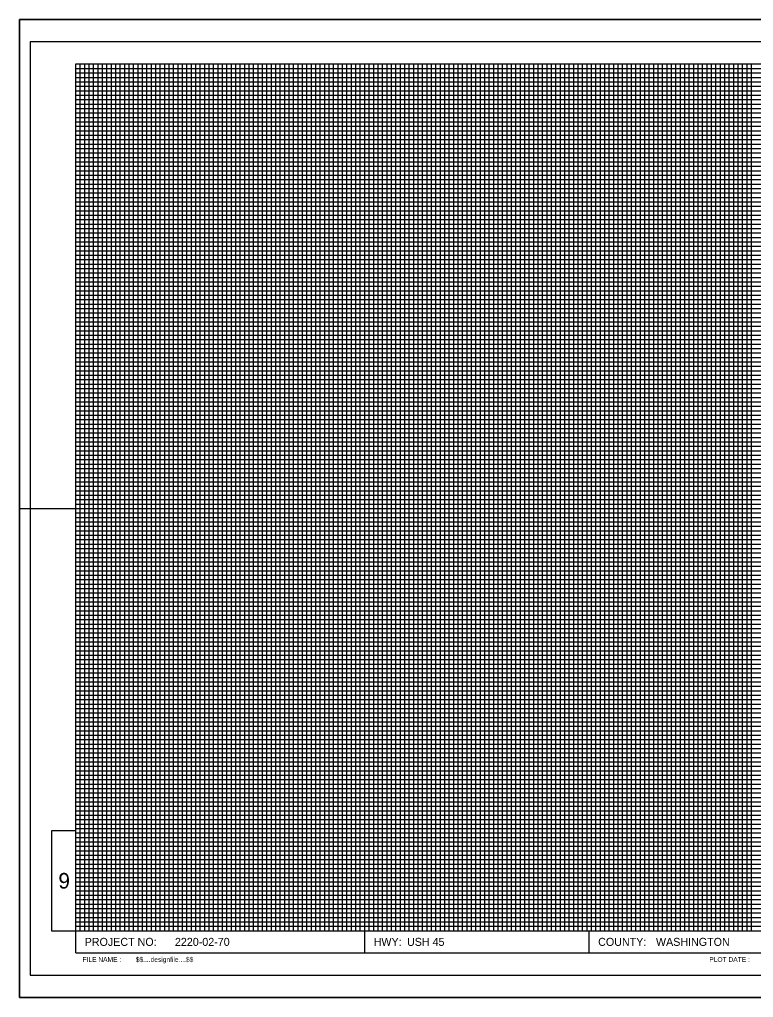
# Model space of a CAD drawing. Extents: x -1703 to 1697, y -1124 to 1076.
# Drawn here: x -1703 to -52, y -1124 to 1076 of the extents above; entities that cross this region are included whole.
import ezdxf

# ---------------------------------------------------------------- set-up
doc = ezdxf.new("R2010")
doc.units = 0
for name, color, linetype in [('E_PROF_Grid', 7, 'Continuous'), ('E_PROF_GridMin', 7, 'Continuous'), ('PLT_Sheet_Border', 7, 'Continuous'), ('PLT_Sheet_Info', 7, 'Continuous')]:
    doc.layers.add(name, color=color, linetype=linetype)

msp = doc.modelspace()

# ---------------------------------------------------------------- linework, layer by layer
at = {"layer": 'E_PROF_Grid'}
for p, q in [((-1526.4, -973.7), (-1526.4, 976.3)), ((-1476.4, -973.7), (-1476.4, 976.3)), ((-1426.4, -973.7), (-1426.4, 976.3)), ((-1376.4, -973.7), (-1376.4, 976.3)), ((-1326.4, -973.7), (-1326.4, 976.3)), ((-1276.4, -973.7), (-1276.4, 976.3)), ((-1226.4, -973.7), (-1226.4, 976.3)), ((-1176.4, -973.7), (-1176.4, 976.3)), ((-1126.4, -973.7), (-1126.4, 976.3)), ((-1076.4, -973.7), (-1076.4, 976.3)), ((-1026.4, -973.7), (-1026.4, 976.3)), ((-976.4, -973.7), (-976.4, 976.3)), ((-926.4, -973.7), (-926.4, 976.3)), ((-876.4, -973.7), (-876.4, 976.3)), ((-826.4, -973.7), (-826.4, 976.3)), ((-776.4, -973.7), (-776.4, 976.3)), ((-726.4, -973.7), (-726.4, 976.3)), ((-676.4, -973.7), (-676.4, 976.3)), ((-626.4, -973.7), (-626.4, 976.3)), ((-576.4, -973.7), (-576.4, 976.3)), ((-526.4, -973.7), (-526.4, 976.3)), ((-476.4, -973.7), (-476.4, 976.3)), ((-426.4, -973.7), (-426.4, 976.3)), ((-376.4, -973.7), (-376.4, 976.3)), ((-326.4, -973.7), (-326.4, 976.3)), ((-276.4, -973.7), (-276.4, 976.3)), ((-226.4, -973.7), (-226.4, 976.3)), ((-176.4, -973.7), (-176.4, 976.3)), ((-126.4, -973.7), (-126.4, 976.3)), ((-76.4, -973.7), (-76.4, 976.3)), ((-1576.4, 926.3), (1573.6, 926.3)), ((-1576.4, 876.3), (1573.6, 876.3)), ((-1576.4, 826.3), (1573.6, 826.3)), ((-1576.4, 776.3), (1573.6, 776.3)), ((-1576.4, 726.3), (1573.6, 726.3)), ((-1576.4, 676.3), (1573.6, 676.3)), ((-1576.4, 626.3), (1573.6, 626.3)), ((-1576.4, 576.3), (1573.6, 576.3)), ((-1576.4, 526.3), (1573.6, 526.3)), ((-1576.4, 476.3), (1573.6, 476.3)), ((-1576.4, 426.3), (1573.6, 426.3)), ((-1576.4, 376.3), (1573.6, 376.3)), ((-1576.4, 326.3), (1573.6, 326.3)), ((-1576.4, 276.3), (1573.6, 276.3)), ((-1576.4, 226.3), (1573.6, 226.3)), ((-1576.4, 176.3), (1573.6, 176.3)), ((-1576.4, 126.3), (1573.6, 126.3)), ((-1576.4, 76.3), (1573.6, 76.3)), ((-1576.4, 26.3), (1573.6, 26.3)), ((-1576.4, -23.7), (1573.6, -23.7)), ((-1576.4, -73.7), (1573.6, -73.7)), ((-1576.4, -123.7), (1573.6, -123.7)), ((-1576.4, -173.7), (1573.6, -173.7)), ((-1576.4, -223.7), (1573.6, -223.7)), ((-1576.4, -273.7), (1573.6, -273.7)), ((-1576.4, -323.7), (1573.6, -323.7)), ((-1576.4, -373.7), (1573.6, -373.7)), ((-1576.4, -423.7), (1573.6, -423.7)), ((-1576.4, -473.7), (1573.6, -473.7)), ((-1576.4, -523.7), (1573.6, -523.7)), ((-1576.4, -573.7), (1573.6, -573.7)), ((-1576.4, -623.7), (1573.6, -623.7)), ((-1576.4, -673.7), (1573.6, -673.7)), ((-1576.4, -723.7), (1573.6, -723.7)), ((-1576.4, -773.7), (1573.6, -773.7)), ((-1576.4, -823.7), (1573.6, -823.7)), ((-1576.4, -873.7), (1573.6, -873.7)), ((-1576.4, -923.7), (1573.6, -923.7))]:
    msp.add_line(p, q, dxfattribs=at)
at = {"layer": 'E_PROF_GridMin'}
for p, q in [((-1566.4, -973.7), (-1566.4, 976.3)), ((-1556.4, -973.7), (-1556.4, 976.3)), ((-1546.4, -973.7), (-1546.4, 976.3)), ((-1536.4, -973.7), (-1536.4, 976.3)), ((-1516.4, -973.7), (-1516.4, 976.3)), ((-1506.4, -973.7), (-1506.4, 976.3)), ((-1496.4, -973.7), (-1496.4, 976.3)), ((-1486.4, -973.7), (-1486.4, 976.3)), ((-1466.4, -973.7), (-1466.4, 976.3)), ((-1456.4, -973.7), (-1456.4, 976.3)), ((-1446.4, -973.7), (-1446.4, 976.3)), ((-1436.4, -973.7), (-1436.4, 976.3)), ((-1416.4, -973.7), (-1416.4, 976.3)), ((-1406.4, -973.7), (-1406.4, 976.3)), ((-1396.4, -973.7), (-1396.4, 976.3)), ((-1386.4, -973.7), (-1386.4, 976.3)), ((-1366.4, -973.7), (-1366.4, 976.3)), ((-1356.4, -973.7), (-1356.4, 976.3)), ((-1346.4, -973.7), (-1346.4, 976.3)), ((-1336.4, -973.7), (-1336.4, 976.3)), ((-1316.4, -973.7), (-1316.4, 976.3)), ((-1306.4, -973.7), (-1306.4, 976.3)), ((-1296.4, -973.7), (-1296.4, 976.3)), ((-1286.4, -973.7), (-1286.4, 976.3)), ((-1266.4, -973.7), (-1266.4, 976.3)), ((-1256.4, -973.7), (-1256.4, 976.3)), ((-1246.4, -973.7), (-1246.4, 976.3)), ((-1236.4, -973.7), (-1236.4, 976.3)), ((-1216.4, -973.7), (-1216.4, 976.3)), ((-1206.4, -973.7), (-1206.4, 976.3)), ((-1196.4, -973.7), (-1196.4, 976.3)), ((-1186.4, -973.7), (-1186.4, 976.3)), ((-1166.4, -973.7), (-1166.4, 976.3)), ((-1156.4, -973.7), (-1156.4, 976.3)), ((-1146.4, -973.7), (-1146.4, 976.3)), ((-1136.4, -973.7), (-1136.4, 976.3)), ((-1116.4, -973.7), (-1116.4, 976.3)), ((-1106.4, -973.7), (-1106.4, 976.3)), ((-1096.4, -973.7), (-1096.4, 976.3)), ((-1086.4, -973.7), (-1086.4, 976.3)), ((-1066.4, -973.7), (-1066.4, 976.3)), ((-1056.4, -973.7), (-1056.4, 976.3)), ((-1046.4, -973.7), (-1046.4, 976.3)), ((-1036.4, -973.7), (-1036.4, 976.3)), ((-1016.4, -973.7), (-1016.4, 976.3)), ((-1006.4, -973.7), (-1006.4, 976.3)), ((-996.4, -973.7), (-996.4, 976.3)), ((-986.4, -973.7), (-986.4, 976.3)), ((-966.4, -973.7), (-966.4, 976.3)), ((-956.4, -973.7), (-956.4, 976.3)), ((-946.4, -973.7), (-946.4, 976.3)), ((-936.4, -973.7), (-936.4, 976.3)), ((-916.4, -973.7), (-916.4, 976.3)), ((-906.4, -973.7), (-906.4, 976.3)), ((-896.4, -973.7), (-896.4, 976.3)), ((-886.4, -973.7), (-886.4, 976.3)), ((-866.4, -973.7), (-866.4, 976.3)), ((-856.4, -973.7), (-856.4, 976.3)), ((-846.4, -973.7), (-846.4, 976.3)), ((-836.4, -973.7), (-836.4, 976.3)), ((-816.4, -973.7), (-816.4, 976.3)), ((-806.4, -973.7), (-806.4, 976.3)), ((-796.4, -973.7), (-796.4, 976.3)), ((-786.4, -973.7), (-786.4, 976.3)), ((-766.4, -973.7), (-766.4, 976.3)), ((-756.4, -973.7), (-756.4, 976.3)), ((-746.4, -973.7), (-746.4, 976.3)), ((-736.4, -973.7), (-736.4, 976.3)), ((-716.4, -973.7), (-716.4, 976.3)), ((-706.4, -973.7), (-706.4, 976.3)), ((-696.4, -973.7), (-696.4, 976.3)), ((-686.4, -973.7), (-686.4, 976.3)), ((-666.4, -973.7), (-666.4, 976.3)), ((-656.4, -973.7), (-656.4, 976.3)), ((-646.4, -973.7), (-646.4, 976.3)), ((-636.4, -973.7), (-636.4, 976.3)), ((-616.4, -973.7), (-616.4, 976.3)), ((-606.4, -973.7), (-606.4, 976.3)), ((-596.4, -973.7), (-596.4, 976.3)), ((-586.4, -973.7), (-586.4, 976.3)), ((-566.4, -973.7), (-566.4, 976.3)), ((-556.4, -973.7), (-556.4, 976.3)), ((-546.4, -973.7), (-546.4, 976.3)), ((-536.4, -973.7), (-536.4, 976.3)), ((-516.4, -973.7), (-516.4, 976.3)), ((-506.4, -973.7), (-506.4, 976.3)), ((-496.4, -973.7), (-496.4, 976.3)), ((-486.4, -973.7), (-486.4, 976.3)), ((-466.4, -973.7), (-466.4, 976.3)), ((-456.4, -973.7), (-456.4, 976.3)), ((-446.4, -973.7), (-446.4, 976.3)), ((-436.4, -973.7), (-436.4, 976.3)), ((-416.4, -973.7), (-416.4, 976.3)), ((-406.4, -973.7), (-406.4, 976.3)), ((-396.4, -973.7), (-396.4, 976.3)), ((-386.4, -973.7), (-386.4, 976.3)), ((-366.4, -973.7), (-366.4, 976.3)), ((-356.4, -973.7), (-356.4, 976.3)), ((-346.4, -973.7), (-346.4, 976.3)), ((-336.4, -973.7), (-336.4, 976.3)), ((-316.4, -973.7), (-316.4, 976.3)), ((-306.4, -973.7), (-306.4, 976.3)), ((-296.4, -973.7), (-296.4, 976.3)), ((-286.4, -973.7), (-286.4, 976.3)), ((-266.4, -973.7), (-266.4, 976.3)), ((-256.4, -973.7), (-256.4, 976.3)), ((-246.4, -973.7), (-246.4, 976.3)), ((-236.4, -973.7), (-236.4, 976.3)), ((-216.4, -973.7), (-216.4, 976.3)), ((-206.4, -973.7), (-206.4, 976.3)), ((-196.4, -973.7), (-196.4, 976.3)), ((-186.4, -973.7), (-186.4, 976.3)), ((-166.4, -973.7), (-166.4, 976.3)), ((-156.4, -973.7), (-156.4, 976.3)), ((-146.4, -973.7), (-146.4, 976.3)), ((-136.4, -973.7), (-136.4, 976.3)), ((-116.4, -973.7), (-116.4, 976.3)), ((-106.4, -973.7), (-106.4, 976.3)), ((-96.4, -973.7), (-96.4, 976.3)), ((-86.4, -973.7), (-86.4, 976.3)), ((-66.4, -973.7), (-66.4, 976.3)), ((-56.4, -973.7), (-56.4, 976.3)), ((-1576.4, 966.3), (1573.6, 966.3)), ((-1576.4, 956.3), (1573.6, 956.3)), ((-1576.4, 946.3), (1573.6, 946.3)), ((-1576.4, 936.3), (1573.6, 936.3)), ((-1576.4, 916.3), (1573.6, 916.3)), ((-1576.4, 906.3), (1573.6, 906.3)), ((-1576.4, 896.3), (1573.6, 896.3)), ((-1576.4, 886.3), (1573.6, 886.3)), ((-1576.4, 866.3), (1573.6, 866.3)), ((-1576.4, 856.3), (1573.6, 856.3)), ((-1576.4, 846.3), (1573.6, 846.3)), ((-1576.4, 836.3), (1573.6, 836.3)), ((-1576.4, 816.3), (1573.6, 816.3)), ((-1576.4, 806.3), (1573.6, 806.3)), ((-1576.4, 796.3), (1573.6, 796.3)), ((-1576.4, 786.3), (1573.6, 786.3)), ((-1576.4, 766.3), (1573.6, 766.3)), ((-1576.4, 756.3), (1573.6, 756.3)), ((-1576.4, 746.3), (1573.6, 746.3)), ((-1576.4, 736.3), (1573.6, 736.3)), ((-1576.4, 716.3), (1573.6, 716.3)), ((-1576.4, 706.3), (1573.6, 706.3)), ((-1576.4, 696.3), (1573.6, 696.3)), ((-1576.4, 686.3), (1573.6, 686.3)), ((-1576.4, 666.3), (1573.6, 666.3)), ((-1576.4, 656.3), (1573.6, 656.3)), ((-1576.4, 646.3), (1573.6, 646.3)), ((-1576.4, 636.3), (1573.6, 636.3)), ((-1576.4, 616.3), (1573.6, 616.3)), ((-1576.4, 606.3), (1573.6, 606.3)), ((-1576.4, 596.3), (1573.6, 596.3)), ((-1576.4, 586.3), (1573.6, 586.3)), ((-1576.4, 566.3), (1573.6, 566.3)), ((-1576.4, 556.3), (1573.6, 556.3)), ((-1576.4, 546.3), (1573.6, 546.3)), ((-1576.4, 536.3), (1573.6, 536.3)), ((-1576.4, 516.3), (1573.6, 516.3)), ((-1576.4, 506.3), (1573.6, 506.3)), ((-1576.4, 496.3), (1573.6, 496.3)), ((-1576.4, 486.3), (1573.6, 486.3)), ((-1576.4, 466.3), (1573.6, 466.3)), ((-1576.4, 456.3), (1573.6, 456.3)), ((-1576.4, 446.3), (1573.6, 446.3)), ((-1576.4, 436.3), (1573.6, 436.3)), ((-1576.4, 416.3), (1573.6, 416.3)), ((-1576.4, 406.3), (1573.6, 406.3)), ((-1576.4, 396.3), (1573.6, 396.3)), ((-1576.4, 386.3), (1573.6, 386.3)), ((-1576.4, 366.3), (1573.6, 366.3)), ((-1576.4, 356.3), (1573.6, 356.3)), ((-1576.4, 346.3), (1573.6, 346.3)), ((-1576.4, 336.3), (1573.6, 336.3)), ((-1576.4, 316.3), (1573.6, 316.3)), ((-1576.4, 306.3), (1573.6, 306.3)), ((-1576.4, 296.3), (1573.6, 296.3)), ((-1576.4, 286.3), (1573.6, 286.3)), ((-1576.4, 266.3), (1573.6, 266.3)), ((-1576.4, 256.3), (1573.6, 256.3)), ((-1576.4, 246.3), (1573.6, 246.3)), ((-1576.4, 236.3), (1573.6, 236.3)), ((-1576.4, 216.3), (1573.6, 216.3)), ((-1576.4, 206.3), (1573.6, 206.3)), ((-1576.4, 196.3), (1573.6, 196.3)), ((-1576.4, 186.3), (1573.6, 186.3)), ((-1576.4, 166.3), (1573.6, 166.3)), ((-1576.4, 156.3), (1573.6, 156.3)), ((-1576.4, 146.3), (1573.6, 146.3)), ((-1576.4, 136.3), (1573.6, 136.3)), ((-1576.4, 116.3), (1573.6, 116.3)), ((-1576.4, 106.3), (1573.6, 106.3)), ((-1576.4, 96.3), (1573.6, 96.3)), ((-1576.4, 86.3), (1573.6, 86.3)), ((-1576.4, 66.3), (1573.6, 66.3)), ((-1576.4, 56.3), (1573.6, 56.3)), ((-1576.4, 46.3), (1573.6, 46.3)), ((-1576.4, 36.3), (1573.6, 36.3)), ((-1576.4, 16.3), (1573.6, 16.3)), ((-1576.4, 6.3), (1573.6, 6.3)), ((-1576.4, -3.7), (1573.6, -3.7)), ((-1576.4, -13.7), (1573.6, -13.7)), ((-1576.4, -33.7), (1573.6, -33.7)), ((-1576.4, -43.7), (1573.6, -43.7)), ((-1576.4, -53.7), (1573.6, -53.7)), ((-1576.4, -63.7), (1573.6, -63.7)), ((-1576.4, -83.7), (1573.6, -83.7)), ((-1576.4, -93.7), (1573.6, -93.7)), ((-1576.4, -103.7), (1573.6, -103.7)), ((-1576.4, -113.7), (1573.6, -113.7)), ((-1576.4, -133.7), (1573.6, -133.7)), ((-1576.4, -143.7), (1573.6, -143.7)), ((-1576.4, -153.7), (1573.6, -153.7)), ((-1576.4, -163.7), (1573.6, -163.7)), ((-1576.4, -183.7), (1573.6, -183.7)), ((-1576.4, -193.7), (1573.6, -193.7)), ((-1576.4, -203.7), (1573.6, -203.7)), ((-1576.4, -213.7), (1573.6, -213.7)), ((-1576.4, -233.7), (1573.6, -233.7)), ((-1576.4, -243.7), (1573.6, -243.7)), ((-1576.4, -253.7), (1573.6, -253.7)), ((-1576.4, -263.7), (1573.6, -263.7)), ((-1576.4, -283.7), (1573.6, -283.7)), ((-1576.4, -293.7), (1573.6, -293.7)), ((-1576.4, -303.7), (1573.6, -303.7)), ((-1576.4, -313.7), (1573.6, -313.7)), ((-1576.4, -333.7), (1573.6, -333.7)), ((-1576.4, -343.7), (1573.6, -343.7)), ((-1576.4, -353.7), (1573.6, -353.7)), ((-1576.4, -363.7), (1573.6, -363.7)), ((-1576.4, -383.7), (1573.6, -383.7)), ((-1576.4, -393.7), (1573.6, -393.7)), ((-1576.4, -403.7), (1573.6, -403.7)), ((-1576.4, -413.7), (1573.6, -413.7)), ((-1576.4, -433.7), (1573.6, -433.7)), ((-1576.4, -443.7), (1573.6, -443.7)), ((-1576.4, -453.7), (1573.6, -453.7)), ((-1576.4, -463.7), (1573.6, -463.7)), ((-1576.4, -483.7), (1573.6, -483.7)), ((-1576.4, -493.7), (1573.6, -493.7)), ((-1576.4, -503.7), (1573.6, -503.7)), ((-1576.4, -513.7), (1573.6, -513.7)), ((-1576.4, -533.7), (1573.6, -533.7)), ((-1576.4, -543.7), (1573.6, -543.7)), ((-1576.4, -553.7), (1573.6, -553.7)), ((-1576.4, -563.7), (1573.6, -563.7)), ((-1576.4, -583.7), (1573.6, -583.7)), ((-1576.4, -593.7), (1573.6, -593.7)), ((-1576.4, -603.7), (1573.6, -603.7)), ((-1576.4, -613.7), (1573.6, -613.7)), ((-1576.4, -633.7), (1573.6, -633.7)), ((-1576.4, -643.7), (1573.6, -643.7)), ((-1576.4, -653.7), (1573.6, -653.7)), ((-1576.4, -663.7), (1573.6, -663.7)), ((-1576.4, -683.7), (1573.6, -683.7)), ((-1576.4, -693.7), (1573.6, -693.7)), ((-1576.4, -703.7), (1573.6, -703.7)), ((-1576.4, -713.7), (1573.6, -713.7)), ((-1576.4, -733.7), (1573.6, -733.7)), ((-1576.4, -743.7), (1573.6, -743.7)), ((-1576.4, -753.7), (1573.6, -753.7)), ((-1576.4, -763.7), (1573.6, -763.7)), ((-1576.4, -783.7), (1573.6, -783.7)), ((-1576.4, -793.7), (1573.6, -793.7)), ((-1576.4, -803.7), (1573.6, -803.7)), ((-1576.4, -813.7), (1573.6, -813.7)), ((-1576.4, -833.7), (1573.6, -833.7)), ((-1576.4, -843.7), (1573.6, -843.7)), ((-1576.4, -853.7), (1573.6, -853.7)), ((-1576.4, -863.7), (1573.6, -863.7)), ((-1576.4, -883.7), (1573.6, -883.7)), ((-1576.4, -893.7), (1573.6, -893.7)), ((-1576.4, -903.7), (1573.6, -903.7)), ((-1576.4, -913.7), (1573.6, -913.7)), ((-1576.4, -933.7), (1573.6, -933.7)), ((-1576.4, -943.7), (1573.6, -943.7)), ((-1576.4, -953.7), (1573.6, -953.7)), ((-1576.4, -963.7), (1573.6, -963.7))]:
    msp.add_line(p, q, dxfattribs=at)
at = {"layer": 'PLT_Sheet_Border'}
for points in [[(-1702.9, 1076.3), (1697.1, 1076.3), (1697.1, -1123.7), (-1702.9, -1123.7)], [(-1702.9, -1123.7), (1697.1, -1123.7), (1697.1, 1076.3), (-1702.9, 1076.3)], [(-1678.9, -1073.7), (1631.1, -1073.7), (1631.1, 1026.3), (-1678.9, 1026.3)]]:
    msp.add_lwpolyline(points, close=True, dxfattribs=at)
at = {"layer": 'PLT_Sheet_Info'}
for p, q in [((-1702.9, 976.3), (-1702.9, 1076.3)), ((-1702.9, 1076.3), (-1602.9, 1076.3)), ((-1576.4, 976.3), (1573.6, 976.3)), ((-1576.4, -1023.7), (-1576.4, 976.3)), ((-1702.9, -73.7), (-1702.9, 26.3)), ((-1702.9, -23.7), (-1576.4, -23.7)), ((-1576.4, -973.7), (1573.6, -973.7)), ((-926.4, -1023.7), (-926.4, -973.7)), ((-421.4, -1023.7), (-421.4, -973.7)), ((-1702.9, -1123.7), (-1702.9, -1023.7)), ((-1576.4, -1023.7), (1573.6, -1023.7)), ((-1702.9, -1123.7), (-1602.9, -1123.7))]:
    msp.add_line(p, q, dxfattribs=at)
msp.add_lwpolyline([(-1576.4, -748.7), (-1631.4, -748.7), (-1631.4, -973.7), (-1576.4, -973.7)], close=True, dxfattribs=at)

# ---------------------------------------------------------------- texts
for s, height, p in [('9', 35, (-1615.6, -878.7)), ('PROJECT NO:', 18, (-1556.4, -1007.7)), ('2220-02-70            ', 18, (-1353.4, -1007.7)), ('HWY:', 18, (-906.4, -1007.7)), ('USH 45              ', 18, (-831.4, -1007.7)), ('COUNTY:', 18, (-401.4, -1007.7)), ('WASHINGTON     ', 18, (-271.4, -1007.7)), ('FILE NAME :', 10.8, (-1561.4, -1043.7))]:
    msp.add_text(s, height=height, dxfattribs=at).set_placement(p)
for s, p in [('$$....designfile....$$', (-1441.4, -1043.7)), ('PLOT DATE :', (-151.4, -1043.7))]:
    msp.add_text(s, height=10.8, rotation=360, dxfattribs=at).set_placement(p)

doc.saveas('drawing.dxf')
